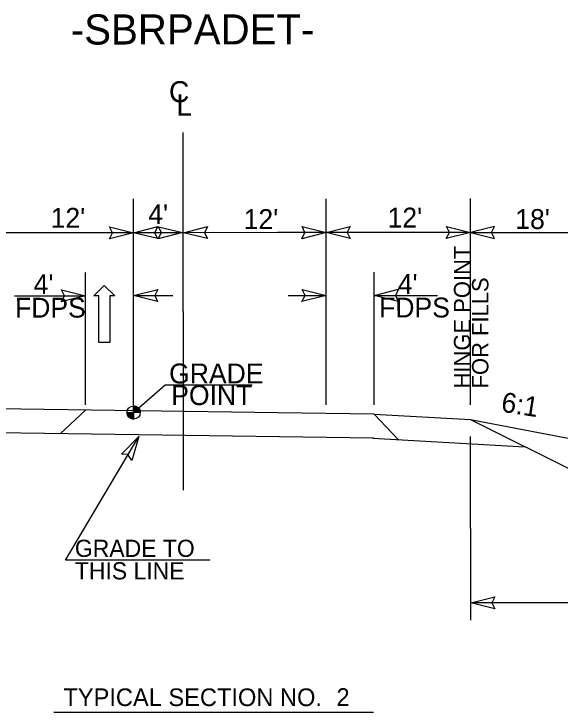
# Model space of a CAD drawing. Extents: x 2241081 to 2251104, y 658534 to 663427.
# Drawn here: x 2241805 to 2242031.9, y 660518.2 to 660808.1 of the extents above; entities that cross this region are included whole.
import ezdxf

# ---------------------------------------------------------------- set-up
doc = ezdxf.new("R2010")
doc.units = 0
for name, color, linetype in [('Old_Level_1', 7, 'Continuous'), ('Old_Level_11', 7, 'Continuous'), ('Old_Level_2', 7, 'Continuous'), ('Old_Level_3', 7, 'Continuous'), ('Prop Dimension Text', 7, 'Continuous'), ('Prop Lane Arrow CELL', 7, 'Continuous'), ('Prop PHM Text', 7, 'Continuous'), ('Typical Grade Point Symbol CELL', 7, 'Continuous'), ('Typical Hinge Slope Interstate CELL', 7, 'Continuous'), ('Typical Terminator CELL', 7, 'Continuous'), ('Typical Text Centerline CELL', 7, 'Continuous'), ('Typical Text Grade Point CELL', 7, 'Continuous'), ('Typical Text Label CELL', 7, 'Continuous')]:
    doc.layers.add(name, color=color, linetype=linetype)

# ---------------------------------------------------------------- blocks, each defined once
blk = doc.blocks.new('TERMINATOR')
at = {"layer": 'Typical Terminator CELL'}
blk.add_lwpolyline([(-0.4687, 0.0807), (0, 0), (-0.4713, -0.0833), (-0.4114, 0)], close=True, dxfattribs=at)

msp = doc.modelspace()

# ---------------------------------------------------------------- linework, layer by layer
at = {"layer": 'Old_Level_1'}
msp.add_line((2241994.7, 660639.7), (2242103.53, 660618.76), dxfattribs=at)
at = {"layer": 'Old_Level_11'}
msp.add_line((2241826.42, 660581.29), (2241856.85, 660632.67), dxfattribs=at)
at = {"layer": 'Old_Level_2'}
for p, q in [((2241914.75, 660642.52), (2241794.73, 660644.19)), ((2241834.74, 660643.63), (2241824.16, 660633.78)), ((2241954.75, 660641.97), (2241914.75, 660642.52)), ((2241954.75, 660641.97), (2241964.61, 660631.4)), ((2241954.75, 660641.97), (2241994.7, 660639.7)), ((2241954.41, 660631.97), (2241775.27, 660634.46)), ((2241954.19, 660631.99), (2242017.29, 660628.41))]:
    msp.add_line(p, q, dxfattribs=at)
at = {"layer": 'Prop Dimension Text'}
for p, q in [((2241854.74, 660645.75), (2241854.69, 660731.34)), ((2241934.74, 660645.8), (2241934.69, 660731.39)), ((2241994.74, 660645.83), (2241994.69, 660731.42)), ((2241994.7, 660717.35), (2241934.7, 660717.32)), ((2241994.7, 660717.35), (2242052.71, 660717.35)), ((2241854.7, 660717.27), (2241794.7, 660717.23)), ((2241875.39, 660717.28), (2241854.7, 660717.27)), ((2241914.7, 660717.3), (2241875.39, 660717.28)), ((2241934.7, 660717.32), (2241914.7, 660717.3)), ((2241834.74, 660645.73), (2241834.71, 660700.81)), ((2241954.74, 660645.81), (2241954.71, 660700.89)), ((2241805.26, 660691.11), (2241834.72, 660691.12)), ((2241854.72, 660691.14), (2241871.09, 660691.15)), ((2241918.98, 660691.18), (2241934.72, 660691.19)), ((2241954.72, 660691.2), (2241981.05, 660691.21)), ((2241994.79, 660556.35), (2241994.74, 660632.68)), ((2241886.42, 660581.33), (2241826.42, 660581.29)), ((2242103.63, 660563.55), (2241994.79, 660563.55))]:
    msp.add_line(p, q, dxfattribs=at)
at = {"layer": 'Prop Lane Arrow CELL'}
for p, q in [((2241838.18, 660691.02), (2241842.45, 660695.36)), ((2241842.45, 660695.36), (2241846.87, 660691.02)), ((2241840.25, 660691.02), (2241838.18, 660691.02)), ((2241840.26, 660671.72), (2241840.25, 660691.02)), ((2241846.87, 660691.02), (2241844.8, 660691.02)), ((2241844.8, 660691.02), (2241844.81, 660671.72)), ((2241844.81, 660671.72), (2241840.26, 660671.72))]:
    msp.add_line(p, q, dxfattribs=at)
at = {"layer": 'Typical Grade Point Symbol CELL'}
for p, q in [((2241854.75, 660645.38), (2241854.74, 660642.63)), ((2241854.74, 660642.63), (2241854.75, 660645.38)), ((2241851.99, 660642.63), (2241854.74, 660642.63)), ((2241854.74, 660642.63), (2241854.74, 660639.87)), ((2241857.5, 660642.63), (2241854.74, 660642.63))]:
    msp.add_line(p, q, dxfattribs=at)
for points in [[(2241854.79, 660642.63), (2241854.79, 660645.38), (2241854.79, 660645.38)], [(2241854.84, 660642.63), (2241854.84, 660645.38)], [(2241854.9, 660642.63), (2241854.9, 660645.37)], [(2241854.95, 660642.63), (2241854.95, 660645.37)], [(2241855.01, 660642.63), (2241855.01, 660645.37)], [(2241855.06, 660642.63), (2241855.06, 660645.36)], [(2241855.12, 660642.63), (2241855.12, 660645.35)], [(2241855.17, 660642.63), (2241855.17, 660645.34)], [(2241855.23, 660642.63), (2241855.23, 660645.34)], [(2241855.28, 660642.63), (2241855.28, 660645.32)], [(2241855.34, 660642.63), (2241855.34, 660645.31)], [(2241855.39, 660642.63), (2241855.39, 660645.3)], [(2241855.45, 660642.63), (2241855.45, 660645.29)], [(2241855.5, 660642.63), (2241855.5, 660645.27)], [(2241855.56, 660642.63), (2241855.56, 660645.26)], [(2241855.61, 660642.63), (2241855.61, 660645.24)], [(2241855.67, 660642.63), (2241855.67, 660645.22)], [(2241855.72, 660642.63), (2241855.72, 660645.2)], [(2241855.78, 660642.63), (2241855.78, 660645.18)], [(2241855.83, 660642.63), (2241855.83, 660645.15)], [(2241855.89, 660642.63), (2241855.89, 660645.13)], [(2241855.94, 660642.63), (2241855.94, 660645.1)], [(2241856, 660642.63), (2241856, 660645.08)], [(2241856.05, 660642.63), (2241856.05, 660645.05)], [(2241856.11, 660642.63), (2241856.11, 660645.02)], [(2241856.16, 660642.63), (2241856.16, 660644.99)], [(2241856.22, 660642.63), (2241856.22, 660644.95)], [(2241856.27, 660642.63), (2241856.27, 660644.91)], [(2241856.33, 660642.63), (2241856.33, 660644.88)], [(2241852.02, 660642.23), (2241852.02, 660642.63)], [(2241852.08, 660641.95), (2241852.08, 660642.63)], [(2241852.13, 660641.76), (2241852.13, 660642.63)], [(2241852.19, 660641.61), (2241852.19, 660642.63)], [(2241852.24, 660641.48), (2241852.24, 660642.63)], [(2241852.3, 660641.37), (2241852.3, 660642.63)], [(2241852.35, 660641.27), (2241852.35, 660642.63)], [(2241852.41, 660641.18), (2241852.41, 660642.63)], [(2241852.46, 660641.09), (2241852.46, 660642.63)], [(2241852.52, 660641.01), (2241852.52, 660642.63)], [(2241852.57, 660640.94), (2241852.57, 660642.63)], [(2241852.63, 660640.87), (2241852.63, 660642.63)], [(2241852.68, 660640.8), (2241852.68, 660642.63)], [(2241852.74, 660640.74), (2241852.74, 660642.63)], [(2241852.79, 660640.69), (2241852.79, 660642.63)], [(2241852.85, 660640.63), (2241852.85, 660642.63)], [(2241852.9, 660640.58), (2241852.9, 660642.63)], [(2241852.96, 660640.53), (2241852.96, 660642.63)], [(2241853.01, 660640.49), (2241853.01, 660642.63)], [(2241853.07, 660640.44), (2241853.07, 660642.63)], [(2241853.12, 660640.41), (2241853.12, 660642.63)], [(2241853.18, 660640.36), (2241853.18, 660642.63)], [(2241853.23, 660640.33), (2241853.23, 660642.63)], [(2241853.29, 660640.29), (2241853.29, 660642.63)], [(2241853.34, 660640.26), (2241853.34, 660642.63)], [(2241853.4, 660640.23), (2241853.4, 660642.63)], [(2241853.45, 660640.2), (2241853.45, 660642.63)], [(2241853.51, 660640.17), (2241853.51, 660642.63)], [(2241853.56, 660640.14), (2241853.56, 660642.63)], [(2241853.62, 660640.12), (2241853.62, 660642.63)], [(2241853.67, 660640.09), (2241853.67, 660642.63)], [(2241853.73, 660640.07), (2241853.73, 660642.63)], [(2241853.78, 660640.04), (2241853.78, 660642.63)], [(2241853.84, 660640.03), (2241853.84, 660642.63)], [(2241853.89, 660640.01), (2241853.89, 660642.63)], [(2241853.95, 660639.99), (2241853.95, 660642.63)], [(2241854, 660639.98), (2241854, 660642.63)], [(2241854.06, 660639.96), (2241854.06, 660642.63)], [(2241854.11, 660639.95), (2241854.11, 660642.63)], [(2241854.17, 660639.93), (2241854.17, 660642.63)], [(2241854.22, 660639.92), (2241854.22, 660642.63)], [(2241854.28, 660639.91), (2241854.28, 660642.63)], [(2241854.33, 660639.9), (2241854.33, 660642.63)], [(2241854.39, 660639.9), (2241854.39, 660642.63)], [(2241854.45, 660639.89), (2241854.45, 660642.63)], [(2241854.5, 660639.89), (2241854.5, 660642.63)], [(2241854.56, 660639.88), (2241854.56, 660642.63)], [(2241854.61, 660639.88), (2241854.61, 660642.63)], [(2241854.67, 660639.87), (2241854.67, 660642.63)], [(2241854.72, 660639.87), (2241854.72, 660639.87), (2241854.72, 660642.63)], [(2241856.38, 660642.63), (2241856.38, 660644.84)], [(2241856.44, 660642.63), (2241856.44, 660644.8)], [(2241856.49, 660642.63), (2241856.49, 660644.75)], [(2241856.55, 660642.63), (2241856.55, 660644.71)], [(2241856.6, 660642.63), (2241856.6, 660644.66)], [(2241856.66, 660642.63), (2241856.66, 660644.61)], [(2241856.71, 660642.63), (2241856.71, 660644.55)], [(2241856.77, 660642.63), (2241856.77, 660644.49)], [(2241856.82, 660642.63), (2241856.82, 660644.43)], [(2241856.88, 660642.63), (2241856.88, 660644.36)], [(2241856.93, 660642.63), (2241856.93, 660644.3)], [(2241856.99, 660642.63), (2241856.99, 660644.22)], [(2241857.04, 660642.63), (2241857.04, 660644.14)], [(2241857.1, 660642.63), (2241857.1, 660644.06)], [(2241857.15, 660642.63), (2241857.15, 660643.96)], [(2241857.21, 660642.63), (2241857.21, 660643.86)], [(2241857.27, 660642.63), (2241857.27, 660643.74)], [(2241857.32, 660642.63), (2241857.32, 660643.61)], [(2241857.38, 660642.63), (2241857.38, 660643.45)], [(2241857.43, 660642.63), (2241857.43, 660643.25)], [(2241857.49, 660642.63), (2241857.49, 660642.93)]]:
    msp.add_lwpolyline(points, dxfattribs=at)
msp.add_circle((2241854.75, 660642.63), 2.75, dxfattribs=at)
for start, end in [(359.9905, 89.9905), (179.9905, 269.9905)]:
    msp.add_arc((2241854.75, 660642.63), 2.75, start, end, dxfattribs=at)
at = {"layer": 'Typical Hinge Slope Interstate CELL'}
msp.add_line((2241994.7, 660639.7), (2242103.57, 660585.27), dxfattribs=at)
at = {"layer": 'Typical Text Centerline CELL'}
msp.add_line((2241875.45, 660610.4), (2241875.36, 660758.95), dxfattribs=at)
at = {"layer": 'Typical Text Grade Point CELL'}
for p, q in [((2241854.74, 660642.63), (2241867.86, 660654.06)), ((2241867.86, 660654.06), (2241903.99, 660654.08))]:
    msp.add_line(p, q, dxfattribs=at)
at = {"layer": 'Typical Text Label CELL'}
msp.add_line((2241821.61, 660518.22), (2241954.47, 660518.22), dxfattribs=at)

# ---------------------------------------------------------------- block references
at = {"layer": 'Typical Terminator CELL'}
for p, xscale, yscale, rotation in [((2241854.7, 660717.27), 21.314641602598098, 30.593161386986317, 0.03488749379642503), ((2241854.7, 660717.27), 21.314641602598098, 30.593161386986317, -179.96511250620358), ((2241875.04, 660717.3), 21.314641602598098, 30.593161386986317, 0.03488749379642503), ((2241875.39, 660717.28), 21.314641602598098, 30.593161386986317, -179.96511250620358), ((2241934.7, 660717.32), 21.314641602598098, 30.593161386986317, 0.03488749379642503), ((2241934.7, 660717.32), 21.314641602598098, 30.593161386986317, -179.96511250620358), ((2241994.7, 660717.35), 21.314641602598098, 30.593161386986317, 0.03488749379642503), ((2241994.7, 660717.35), 21.314641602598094, -30.59316138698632, 179.96498243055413), ((2241834.72, 660691.12), 21.314641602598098, 30.593161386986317, 0.03488749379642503), ((2241854.72, 660691.14), 21.314641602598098, 30.593161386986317, -179.96511250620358), ((2241934.72, 660691.19), 21.314641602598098, 30.593161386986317, 0.03488749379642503), ((2241954.72, 660691.2), 21.314641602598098, 30.593161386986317, -179.96511250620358), ((2241856.85, 660632.67), 21.314641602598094, 30.59316138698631, 59.36798649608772), ((2241994.79, 660563.55), 21.314641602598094, 30.593161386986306, -179.96511250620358)]:
    msp.add_blockref('TERMINATOR', p, dxfattribs=dict(at, xscale=xscale, yscale=yscale, rotation=rotation))

# ---------------------------------------------------------------- texts
at = {"layer": 'Old_Level_3'}
for s, p in [('GRADE TO', (2241830.32, 660582.64)), ('THIS LINE', (2241830.32, 660573.29))]:
    msp.add_text(s, height=7.131, rotation=359.9999, dxfattribs=at).set_placement(p)
at = {"layer": 'Prop Dimension Text'}
for s, height, rotation, p in [('-SBRPADET-', 12.5, 0.0349, (2241828.63, 660795.41)), ("4'", 8.25, 0.0349, (2241860.81, 660720.82)), ("12'", 8.25, 0.0349, (2241820.26, 660719.33)), ("12'", 8.25, 0.0349, (2241900.46, 660718.8)), ("12'", 8.25, 0.0349, (2241960.26, 660719.42)), ("18'", 8.25, 359.9999, (2242013.32, 660718.82)), ("4'", 8.25, 0.0349, (2241813.2, 660691.79)), ("4'", 8.25, 0.0349, (2241964.49, 660691.85)), ('FDPS', 8.25, 0.0349, (2241805.44, 660682)), ('FDPS', 8.25, 0.0349, (2241956.74, 660682.06)), ('6:1', 8.25, 351.1342, (2242007.13, 660643.02))]:
    msp.add_text(s, height=height, rotation=rotation, dxfattribs=at).set_placement(p)
at = {"layer": 'Prop PHM Text'}
for s, height, p in [('HINGE POINT', 6.8193, (2241994.65, 660652.6)), ('FOR FILLS', 6.819, (2242002.16, 660652.6))]:
    msp.add_text(s, height=height, rotation=89.9999, dxfattribs=at).set_placement(p)
at = {"layer": 'Typical Text Centerline CELL'}
for s, rotation, p in [('C', 0.0349, (2241869.42, 660771.43)), ('L', 359.9818, (2241872.45, 660765.93))]:
    msp.add_text(s, height=8.76, rotation=rotation, dxfattribs=at).set_placement(p)
at = {"layer": 'Typical Text Grade Point CELL'}
for s, p in [('GRADE', (2241869.48, 660654.68)), ('POINT', (2241870.36, 660645.68))]:
    msp.add_text(s, height=8.25, rotation=0.0349, dxfattribs=at).set_placement(p)
at = {"layer": 'Typical Text Label CELL'}
for s, height, p in [('TYPICAL SECTION NO.  ', 7.3404, (2241825.55, 660520.68)), ('2 ', 7.34, (2241939.03, 660520.77))]:
    msp.add_text(s, height=height, dxfattribs=at).set_placement(p)

doc.saveas('drawing.dxf')
